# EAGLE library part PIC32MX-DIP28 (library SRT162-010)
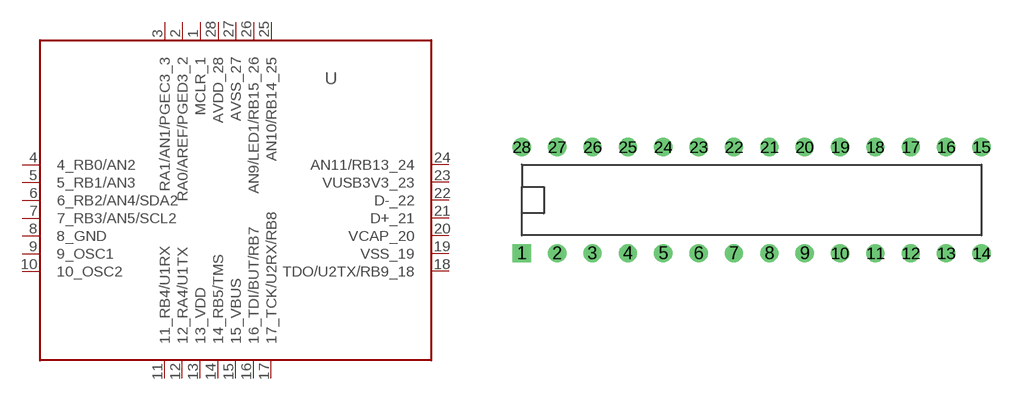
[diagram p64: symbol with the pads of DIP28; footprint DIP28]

Designator prefix U

## PIC32MX-DIP28  [DIP28]
1  MCLR_1  pas
2  RA0/AREF/PGED3_2  pas
3  RA1/AN1/PGEC3_3  pas
4  4_RB0/AN2  pas
5  5_RB1/AN3  pas
6  6_RB2/AN4/SDA2  pas
7  7_RB3/AN5/SCL2  pas
8  8_GND  pwr
9  9_OSC1  pas
10  10_OSC2  pas
11  11_RB4/U1RX  pas
12  12_RA4/U1TX  pas
13  13_VDD  pwr
14  14_RB5/TMS  pas
15  15_VBUS  pas
16  16_TDI/BUT/RB7  pas
17  17_TCK/U2RX/RB8  pas
18  TDO/U2TX/RB9_18  pas
19  VSS_19  pwr
20  VCAP_20  sup
21  D+_21  pas
22  D-_22  pas
23  VUSB3V3_23  pwr
24  AN11/RB13_24  pas
25  AN10/RB14_25  pas
26  AN9/LED1/RB15_26  pas
27  AVSS_27  pwr
28  AVDD_28  pwr

## Footprint DIP28 (pad centres in mm)
drill 0.8 square: 1 -16.51,-3.81
drill 0.8 round: 2 -13.97,-3.81; 3 -11.43,-3.81; 4 -8.89,-3.81; 5 -6.35,-3.81; 6 -3.81,-3.81; 7 -1.27,-3.81; 8 1.27,-3.81; 9 3.81,-3.81; 10 6.35,-3.81; 11 8.89,-3.81; 12 11.43,-3.81; 13 13.97,-3.81; 14 16.51,-3.81; 15 16.51,3.81; 16 13.97,3.81; 17 11.43,3.81; 18 8.89,3.81; 19 6.35,3.81; 20 3.81,3.81; 21 1.27,3.81; 22 -1.27,3.81; 23 -3.81,3.81; 24 -6.35,3.81; 25 -8.89,3.81; 26 -11.43,3.81; 27 -13.97,3.81; 28 -16.51,3.81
